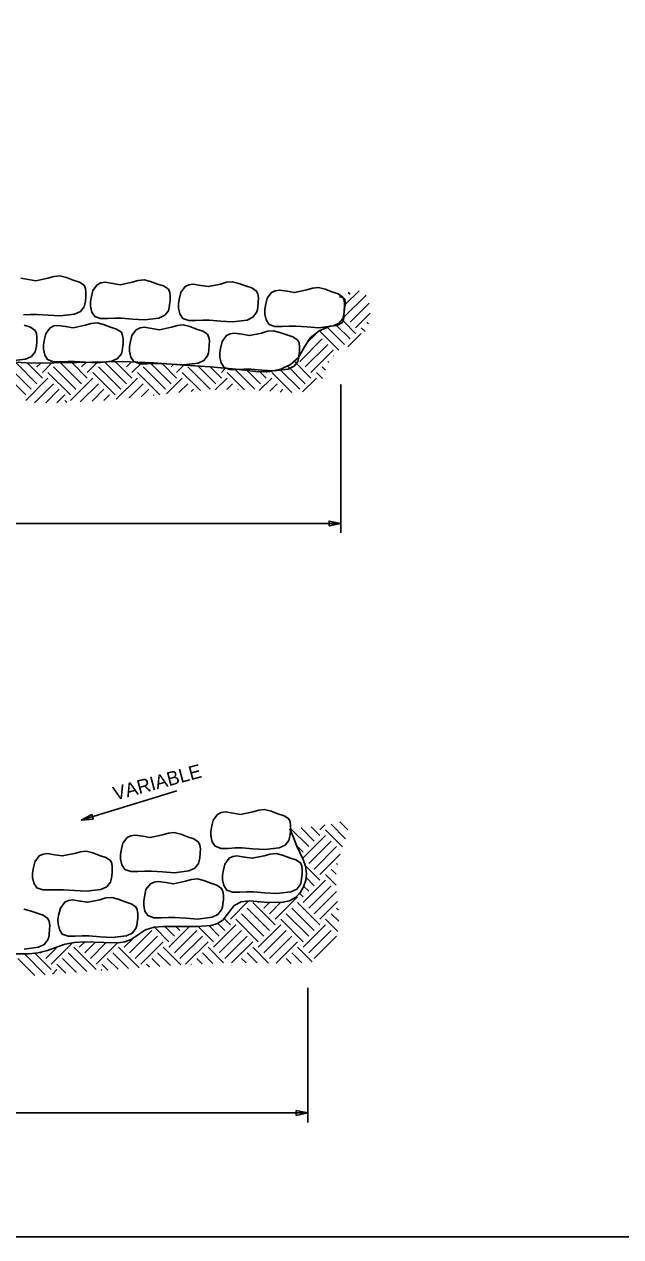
# Model space of a CAD drawing. Extents: x -439.1 to -407.9, y -458.1 to -436.2.
# Drawn here: x -424.86 to -418.4, y -458.05 to -444.91 of the extents above; entities that cross this region are included whole.
import ezdxf

# ---------------------------------------------------------------- set-up
doc = ezdxf.new("R2010")
doc.units = 0
doc.layers.add('Draft_Named_Boundary', color=7, linetype='Continuous')
doc.layers.add('Level 4', color=7, linetype='Continuous')

msp = doc.modelspace()

# ---------------------------------------------------------------- linework, layer by layer
at = {"layer": 'Draft_Named_Boundary'}
msp.add_lwpolyline([(-439.109, -458.051), (-407.859, -458.051), (-407.859, -437.676), (-439.109, -437.676)], close=True, dxfattribs=at)
at = {"layer": 'Level 4'}
for p, q in [((-421.415, -447.871), (-421.429, -447.856)), ((-421.389, -448.078), (-421.155, -447.844)), ((-421.38, -447.947), (-421.231, -447.798)), ((-421.329, -447.835), (-421.348, -447.816)), ((-421.329, -448.138), (-421.121, -447.931)), ((-421.268, -448.26), (-421.405, -448.123)), ((-421.268, -448.199), (-421.111, -448.042)), ((-421.799, -448.366), (-421.692, -448.26)), ((-421.45, -448.441), (-421.66, -448.231)), ((-421.389, -448.381), (-421.578, -448.193)), ((-421.329, -448.32), (-421.474, -448.174)), ((-421.352, -448.404), (-421.208, -448.26)), ((-421.166, -448.241), (-421.208, -448.199)), ((-421.129, -448.156), (-421.147, -448.138)), ((-421.874, -448.563), (-421.632, -448.32)), ((-421.814, -448.623), (-421.571, -448.381)), ((-421.753, -448.684), (-421.511, -448.441)), ((-421.508, -448.505), (-421.511, -448.502)), ((-424.784, -448.866), (-425.026, -448.623)), ((-424.723, -448.805), (-424.952, -448.576)), ((-424.663, -448.744), (-424.824, -448.583)), ((-424.723, -448.623), (-424.685, -448.585)), ((-424.663, -448.684), (-424.563, -448.584)), ((-424.299, -448.866), (-424.541, -448.623)), ((-424.238, -448.805), (-424.462, -448.581)), ((-424.178, -448.744), (-424.345, -448.577)), ((-424.238, -448.623), (-424.185, -448.57)), ((-424.178, -448.684), (-424.06, -448.566)), ((-423.814, -448.866), (-424.056, -448.623)), ((-423.753, -448.805), (-423.994, -448.564)), ((-423.693, -448.744), (-423.874, -448.563)), ((-423.753, -448.623), (-423.698, -448.568)), ((-423.693, -448.684), (-423.583, -448.574)), ((-423.329, -448.866), (-423.571, -448.623)), ((-423.268, -448.805), (-423.495, -448.578)), ((-423.208, -448.744), (-423.365, -448.587)), ((-423.268, -448.623), (-423.242, -448.596)), ((-423.208, -448.684), (-423.129, -448.605)), ((-422.844, -448.866), (-423.087, -448.623)), ((-422.783, -448.805), (-422.974, -448.615)), ((-422.723, -448.744), (-422.844, -448.623)), ((-422.723, -448.684), (-422.677, -448.638)), ((-422.359, -448.866), (-422.578, -448.647)), ((-421.874, -448.866), (-422.09, -448.65)), ((-421.814, -448.805), (-422.003, -448.615)), ((-421.753, -448.744), (-421.932, -448.565)), ((-421.595, -448.66), (-421.632, -448.623)), ((-421.56, -448.574), (-421.571, -448.563)), ((-424.844, -448.926), (-425.087, -448.684)), ((-424.844, -448.987), (-424.602, -448.744)), ((-424.359, -448.926), (-424.602, -448.684)), ((-424.359, -448.987), (-424.117, -448.744)), ((-423.875, -448.926), (-424.117, -448.684)), ((-423.862, -448.974), (-423.632, -448.744)), ((-423.391, -448.925), (-423.632, -448.684)), ((-423.319, -448.916), (-423.147, -448.744)), ((-422.951, -448.88), (-423.147, -448.684)), ((-422.79, -448.873), (-422.662, -448.744)), ((-422.474, -448.872), (-422.662, -448.684)), ((-422.299, -448.805), (-422.439, -448.664)), ((-422.312, -448.879), (-422.177, -448.744)), ((-422.238, -448.744), (-422.308, -448.675)), ((-422.238, -448.684), (-422.227, -448.673)), ((-421.959, -448.902), (-422.177, -448.684)), ((-421.843, -448.895), (-421.692, -448.744)), ((-421.628, -448.748), (-421.692, -448.684)), ((-424.748, -449.011), (-424.541, -448.805)), ((-424.627, -449.012), (-424.481, -448.866)), ((-424.253, -449.001), (-424.056, -448.805)), ((-424.125, -448.995), (-423.996, -448.866)), ((-423.727, -448.961), (-423.571, -448.805)), ((-423.593, -448.948), (-423.511, -448.866)), ((-423.183, -448.902), (-423.087, -448.805)), ((-423.049, -448.889), (-423.026, -448.866)), ((-422.664, -448.868), (-422.602, -448.805)), ((-422.544, -448.869), (-422.541, -448.866)), ((-422.198, -448.887), (-422.117, -448.805)), ((-422.087, -448.896), (-422.056, -448.866)), ((-421.43, -448.814), (-421.43, -450.423)), ((-424.507, -449.014), (-424.42, -448.926)), ((-424.398, -449.009), (-424.42, -448.987)), ((-423.996, -448.987), (-423.935, -448.926)), ((-423.457, -448.933), (-423.45, -448.926)), ((-421.43, -450.321), (-436.149, -450.321)), ((-424.241, -453.535), (-423.205, -453.219)), ((-421.777, -453.822), (-421.972, -453.628)), ((-421.717, -453.762), (-421.86, -453.619)), ((-421.656, -453.701), (-421.749, -453.608)), ((-421.656, -453.64), (-421.601, -453.586)), ((-421.41, -453.826), (-421.596, -453.64)), ((-421.378, -453.737), (-421.535, -453.58)), ((-421.354, -453.639), (-421.439, -453.555)), ((-421.838, -453.943), (-421.596, -453.701)), ((-421.777, -454.004), (-421.535, -453.762)), ((-421.838, -453.883), (-421.903, -453.818)), ((-421.717, -454.065), (-421.474, -453.822)), ((-421.656, -454.125), (-421.437, -453.906)), ((-421.656, -454.186), (-421.821, -454.021)), ((-421.463, -454.015), (-421.474, -454.004)), ((-421.717, -454.246), (-421.809, -454.155)), ((-421.48, -454.241), (-421.596, -454.125)), ((-421.48, -454.12), (-421.535, -454.065)), ((-421.838, -454.428), (-421.596, -454.186)), ((-421.777, -454.307), (-421.831, -454.254)), ((-421.777, -454.489), (-421.535, -454.246)), ((-422.626, -454.61), (-422.431, -454.415)), ((-422.141, -454.671), (-422.384, -454.428)), ((-422.323, -454.428), (-422.312, -454.418)), ((-422.262, -454.489), (-422.2, -454.427)), ((-422.202, -454.55), (-422.078, -454.426)), ((-422.141, -454.61), (-421.899, -454.368)), ((-421.656, -454.671), (-421.899, -454.428)), ((-421.838, -454.368), (-421.882, -454.324)), ((-421.717, -454.55), (-421.476, -454.308)), ((-421.656, -454.61), (-421.464, -454.418)), ((-422.262, -454.792), (-422.505, -454.55)), ((-422.202, -454.731), (-422.444, -454.489)), ((-421.777, -454.792), (-422.02, -454.55)), ((-421.717, -454.731), (-421.959, -454.489)), ((-421.452, -454.632), (-421.535, -454.55)), ((-421.453, -454.51), (-421.474, -454.489)), ((-423.293, -454.853), (-423.449, -454.696)), ((-423.232, -454.792), (-423.336, -454.688)), ((-423.293, -454.913), (-423.068, -454.688)), ((-423.172, -454.731), (-423.216, -454.687)), ((-422.808, -454.853), (-422.973, -454.687)), ((-422.747, -454.792), (-422.86, -454.679)), ((-422.808, -454.913), (-422.565, -454.671)), ((-422.687, -454.731), (-422.77, -454.648)), ((-422.626, -454.671), (-422.694, -454.603)), ((-422.323, -454.853), (-422.565, -454.61)), ((-422.323, -454.913), (-422.08, -454.671)), ((-421.838, -454.853), (-422.08, -454.61)), ((-421.838, -454.913), (-421.596, -454.671)), ((-421.462, -454.743), (-421.596, -454.61)), ((-423.778, -454.913), (-423.677, -454.813)), ((-423.717, -454.974), (-423.475, -454.731)), ((-423.656, -455.034), (-423.414, -454.792)), ((-423.232, -454.974), (-422.99, -454.731)), ((-423.172, -455.034), (-422.929, -454.792)), ((-422.747, -454.974), (-422.505, -454.731)), ((-422.687, -455.034), (-422.444, -454.792)), ((-422.262, -454.974), (-422.02, -454.731)), ((-422.202, -455.034), (-421.959, -454.792)), ((-421.777, -454.974), (-421.535, -454.731)), ((-421.717, -455.034), (-421.474, -454.792)), ((-424.687, -454.974), (-424.674, -454.961)), ((-424.626, -455.034), (-424.503, -454.911)), ((-424.566, -455.095), (-424.341, -454.87)), ((-424.081, -455.156), (-424.323, -454.913)), ((-424.263, -454.913), (-424.203, -454.854)), ((-424.202, -454.974), (-424.087, -454.859)), ((-424.141, -455.034), (-423.97, -454.863)), ((-424.081, -455.095), (-423.85, -454.865)), ((-423.615, -455.136), (-423.838, -454.913)), ((-423.778, -454.853), (-423.781, -454.849)), ((-423.596, -455.095), (-423.353, -454.853)), ((-423.161, -455.105), (-423.353, -454.913)), ((-423.111, -455.095), (-422.868, -454.853)), ((-422.699, -455.082), (-422.868, -454.913)), ((-422.614, -455.083), (-422.384, -454.853)), ((-422.213, -455.084), (-422.384, -454.913)), ((-422.13, -455.084), (-421.899, -454.853)), ((-421.741, -455.071), (-421.899, -454.913)), ((-424.744, -455.22), (-424.929, -455.034)), ((-424.632, -455.211), (-424.857, -454.985)), ((-424.566, -455.156), (-424.747, -454.974)), ((-424.294, -455.185), (-424.444, -455.034)), ((-424.181, -455.177), (-424.384, -454.974)), ((-423.842, -455.152), (-423.96, -455.034)), ((-423.728, -455.144), (-423.899, -454.974)), ((-423.389, -455.12), (-423.475, -455.034)), ((-423.276, -455.112), (-423.414, -454.974)), ((-422.93, -455.094), (-422.99, -455.034)), ((-422.815, -455.088), (-422.929, -454.974)), ((-422.456, -455.083), (-422.505, -455.034)), ((-422.335, -455.083), (-422.444, -454.974)), ((-421.966, -455.088), (-422.02, -455.034)), ((-421.85, -455.083), (-421.959, -454.974)), ((-424.554, -455.205), (-424.505, -455.156)), ((-424.407, -455.193), (-424.505, -455.095)), ((-424.03, -455.166), (-424.02, -455.156)), ((-423.955, -455.16), (-424.02, -455.095)), ((-423.502, -455.128), (-423.535, -455.095)), ((-423.046, -455.1), (-423.05, -455.095)), ((-421.785, -455.352), (-421.785, -456.812)), ((-421.785, -456.709), (-435.084, -456.709))]:
    msp.add_line(p, q, dxfattribs=at)
for points in [[(-424.897, -447.663), (-424.815, -447.675), (-424.733, -447.689), (-424.602, -447.661), (-424.537, -447.642), (-424.473, -447.637), (-424.403, -447.655), (-424.329, -447.683), (-424.262, -447.703), (-424.211, -447.738), (-424.196, -447.772), (-424.191, -447.811), (-424.192, -447.86), (-424.197, -447.909), (-424.202, -447.942), (-424.211, -447.972), (-424.251, -448.022), (-424.314, -448.052), (-424.47, -448.07), (-424.6, -448.063), (-424.72, -448.054), (-424.792, -448.054), (-424.868, -448.057)], [(-421.548, -448.181), (-421.473, -448.176), (-421.414, -448.145), (-421.4, -448.117), (-421.395, -448.082), (-421.391, -448), (-421.377, -447.939), (-421.385, -447.89), (-421.41, -447.872), (-421.442, -447.862)], [(-421.548, -448.181), (-421.664, -448.231), (-421.76, -448.308), (-421.825, -448.413), (-421.888, -448.521), (-421.973, -448.598), (-422.079, -448.648), (-422.198, -448.673), (-422.32, -448.675), (-422.567, -448.648), (-422.845, -448.623), (-423.119, -448.606), (-423.459, -448.58), (-423.799, -448.563), (-424.288, -448.575), (-424.776, -448.584), (-425.211, -448.556)], [(-424.86, -448.171), (-424.793, -448.192), (-424.741, -448.227), (-424.727, -448.26), (-424.722, -448.299), (-424.723, -448.349), (-424.728, -448.398), (-424.733, -448.43), (-424.741, -448.46), (-424.781, -448.51), (-424.845, -448.54), (-425.001, -448.559)], [(-421.98, -453.628), (-421.943, -453.722), (-421.904, -453.816), (-421.836, -453.961), (-421.81, -454.035), (-421.799, -454.113), (-421.807, -454.187), (-421.832, -454.259), (-421.871, -454.323), (-421.921, -454.374), (-421.985, -454.409), (-422.057, -454.426), (-422.218, -454.427), (-422.42, -454.411), (-422.51, -454.422), (-422.584, -454.461), (-422.645, -454.539), (-422.706, -454.618), (-422.765, -454.656), (-422.834, -454.677), (-422.985, -454.688), (-423.17, -454.687), (-423.352, -454.688), (-423.45, -454.696), (-423.544, -454.723), (-423.623, -454.775), (-423.7, -454.828), (-423.769, -454.853), (-423.842, -454.865), (-423.997, -454.863), (-424.211, -454.854), (-424.315, -454.86), (-424.416, -454.88), (-424.511, -454.914), (-424.608, -454.95), (-424.709, -454.974), (-424.814, -454.985), (-425.026, -454.985)], [(-424.865, -454.499), (-424.795, -454.517), (-424.721, -454.545), (-424.653, -454.566), (-424.602, -454.601), (-424.588, -454.635), (-424.583, -454.673), (-424.584, -454.723), (-424.589, -454.772), (-424.594, -454.804), (-424.602, -454.834), (-424.642, -454.884), (-424.706, -454.914), (-424.862, -454.933)]]:
    msp.add_lwpolyline(points, dxfattribs=at)
for points in [[(-424.135, -447.873), (-424.117, -447.794), (-424.07, -447.732), (-424.029, -447.712), (-423.984, -447.705), (-423.901, -447.718), (-423.82, -447.732), (-423.689, -447.704), (-423.624, -447.685), (-423.56, -447.679), (-423.49, -447.697), (-423.416, -447.725), (-423.349, -447.746), (-423.297, -447.781), (-423.283, -447.815), (-423.278, -447.853), (-423.279, -447.903), (-423.284, -447.952), (-423.289, -447.984), (-423.297, -448.014), (-423.337, -448.064), (-423.401, -448.094), (-423.557, -448.113), (-423.687, -448.106), (-423.807, -448.096), (-423.878, -448.096), (-423.955, -448.1), (-424.032, -448.1), (-424.096, -448.077), (-424.128, -448.028), (-424.142, -447.965), (-424.143, -447.918), (-424.135, -447.873)], [(-423.18, -447.894), (-423.161, -447.816), (-423.114, -447.753), (-423.074, -447.733), (-423.029, -447.727), (-422.946, -447.739), (-422.864, -447.753), (-422.733, -447.725), (-422.668, -447.706), (-422.605, -447.7), (-422.534, -447.718), (-422.46, -447.746), (-422.393, -447.767), (-422.342, -447.802), (-422.327, -447.836), (-422.322, -447.874), (-422.323, -447.924), (-422.329, -447.973), (-422.333, -448.005), (-422.342, -448.035), (-422.382, -448.085), (-422.445, -448.115), (-422.601, -448.134), (-422.731, -448.127), (-422.851, -448.118), (-422.923, -448.118), (-422.999, -448.121), (-423.076, -448.121), (-423.14, -448.098), (-423.172, -448.049), (-423.186, -447.986), (-423.187, -447.939), (-423.18, -447.894)], [(-422.245, -447.958), (-422.227, -447.879), (-422.18, -447.817), (-422.139, -447.797), (-422.094, -447.79), (-422.011, -447.803), (-421.93, -447.817), (-421.798, -447.789), (-421.734, -447.77), (-421.67, -447.764), (-421.6, -447.782), (-421.526, -447.81), (-421.459, -447.831), (-421.407, -447.866), (-421.393, -447.899), (-421.388, -447.938), (-421.389, -447.988), (-421.394, -448.037), (-421.399, -448.069), (-421.407, -448.099), (-421.447, -448.149), (-421.511, -448.179), (-421.667, -448.198), (-421.797, -448.19), (-421.917, -448.181), (-421.988, -448.181), (-422.065, -448.185), (-422.142, -448.185), (-422.206, -448.162), (-422.238, -448.113), (-422.252, -448.05), (-422.253, -448.003), (-422.245, -447.958)], [(-424.645, -448.34), (-424.627, -448.261), (-424.579, -448.199), (-424.539, -448.179), (-424.494, -448.173), (-424.411, -448.185), (-424.33, -448.199), (-424.198, -448.171), (-424.133, -448.152), (-424.07, -448.146), (-423.999, -448.164), (-423.925, -448.192), (-423.858, -448.213), (-423.807, -448.248), (-423.793, -448.282), (-423.787, -448.32), (-423.788, -448.37), (-423.794, -448.419), (-423.799, -448.451), (-423.807, -448.481), (-423.847, -448.531), (-423.91, -448.561), (-424.067, -448.58), (-424.197, -448.573), (-424.316, -448.564), (-424.388, -448.564), (-424.464, -448.567), (-424.541, -448.567), (-424.606, -448.544), (-424.638, -448.495), (-424.652, -448.432), (-424.652, -448.385), (-424.645, -448.34)], [(-423.711, -448.361), (-423.692, -448.283), (-423.645, -448.22), (-423.604, -448.201), (-423.559, -448.194), (-423.477, -448.206), (-423.395, -448.22), (-423.264, -448.192), (-423.199, -448.173), (-423.136, -448.167), (-423.065, -448.186), (-422.991, -448.213), (-422.924, -448.234), (-422.873, -448.269), (-422.858, -448.303), (-422.853, -448.342), (-422.854, -448.391), (-422.86, -448.44), (-422.864, -448.472), (-422.873, -448.503), (-422.913, -448.553), (-422.976, -448.583), (-423.132, -448.601), (-423.262, -448.594), (-423.382, -448.585), (-423.454, -448.585), (-423.53, -448.588), (-423.607, -448.588), (-423.671, -448.565), (-423.703, -448.516), (-423.717, -448.453), (-423.718, -448.406), (-423.711, -448.361)], [(-422.734, -448.425), (-422.715, -448.346), (-422.668, -448.284), (-422.628, -448.264), (-422.583, -448.257), (-422.5, -448.27), (-422.418, -448.284), (-422.287, -448.256), (-422.222, -448.237), (-422.159, -448.231), (-422.088, -448.249), (-422.014, -448.277), (-421.947, -448.298), (-421.896, -448.333), (-421.881, -448.367), (-421.876, -448.405), (-421.877, -448.455), (-421.883, -448.504), (-421.887, -448.536), (-421.896, -448.566), (-421.936, -448.616), (-421.999, -448.646), (-422.155, -448.665), (-422.285, -448.658), (-422.405, -448.648), (-422.477, -448.649), (-422.553, -448.652), (-422.63, -448.652), (-422.694, -448.629), (-422.726, -448.58), (-422.74, -448.517), (-422.741, -448.47), (-422.734, -448.425)], [(-421.556, -450.347), (-421.43, -450.321), (-421.556, -450.294)], [(-424.128, -453.473), (-424.241, -453.535), (-424.113, -453.524)], [(-424.128, -453.473), (-424.241, -453.535), (-424.113, -453.524)], [(-422.83, -453.614), (-422.812, -453.535), (-422.764, -453.473), (-422.724, -453.453), (-422.679, -453.446), (-422.596, -453.459), (-422.515, -453.473), (-422.383, -453.445), (-422.318, -453.426), (-422.255, -453.42), (-422.185, -453.438), (-422.111, -453.466), (-422.043, -453.487), (-421.992, -453.522), (-421.978, -453.555), (-421.973, -453.594), (-421.974, -453.644), (-421.979, -453.693), (-421.984, -453.725), (-421.992, -453.755), (-422.032, -453.805), (-422.096, -453.835), (-422.252, -453.854), (-422.382, -453.846), (-422.502, -453.837), (-422.573, -453.837), (-422.649, -453.841), (-422.727, -453.841), (-422.791, -453.818), (-422.823, -453.769), (-422.837, -453.706), (-422.838, -453.659), (-422.83, -453.614)], [(-423.809, -453.865), (-423.791, -453.786), (-423.743, -453.724), (-423.703, -453.704), (-423.658, -453.697), (-423.575, -453.71), (-423.494, -453.724), (-423.362, -453.696), (-423.297, -453.677), (-423.234, -453.671), (-423.163, -453.689), (-423.089, -453.717), (-423.022, -453.738), (-422.971, -453.773), (-422.957, -453.806), (-422.951, -453.845), (-422.952, -453.895), (-422.958, -453.944), (-422.963, -453.976), (-422.971, -454.006), (-423.011, -454.056), (-423.074, -454.086), (-423.231, -454.105), (-423.361, -454.097), (-423.48, -454.088), (-423.552, -454.088), (-423.628, -454.092), (-423.705, -454.092), (-423.77, -454.069), (-423.802, -454.02), (-423.816, -453.957), (-423.816, -453.91), (-423.809, -453.865)], [(-424.763, -454.066), (-424.744, -453.987), (-424.697, -453.924), (-424.656, -453.905), (-424.611, -453.898), (-424.529, -453.91), (-424.447, -453.924), (-424.316, -453.896), (-424.251, -453.878), (-424.188, -453.872), (-424.117, -453.89), (-424.043, -453.918), (-423.976, -453.939), (-423.925, -453.974), (-423.91, -454.007), (-423.905, -454.046), (-423.906, -454.095), (-423.912, -454.144), (-423.916, -454.177), (-423.925, -454.207), (-423.965, -454.257), (-424.028, -454.287), (-424.184, -454.305), (-424.314, -454.298), (-424.434, -454.289), (-424.506, -454.289), (-424.582, -454.292), (-424.659, -454.292), (-424.723, -454.269), (-424.755, -454.22), (-424.769, -454.158), (-424.77, -454.111), (-424.763, -454.066)], [(-422.705, -454.091), (-422.686, -454.012), (-422.639, -453.949), (-422.599, -453.93), (-422.554, -453.923), (-422.471, -453.935), (-422.389, -453.949), (-422.258, -453.921), (-422.193, -453.903), (-422.13, -453.897), (-422.059, -453.915), (-421.985, -453.943), (-421.918, -453.964), (-421.867, -453.999), (-421.852, -454.032), (-421.847, -454.071), (-421.848, -454.121), (-421.854, -454.17), (-421.858, -454.202), (-421.867, -454.232), (-421.907, -454.282), (-421.97, -454.312), (-422.126, -454.331), (-422.256, -454.323), (-422.376, -454.314), (-422.448, -454.314), (-422.524, -454.317), (-422.601, -454.317), (-422.665, -454.294), (-422.698, -454.245), (-422.711, -454.183), (-422.712, -454.136), (-422.705, -454.091)], [(-423.558, -454.367), (-423.54, -454.288), (-423.492, -454.225), (-423.452, -454.206), (-423.407, -454.199), (-423.324, -454.212), (-423.243, -454.225), (-423.111, -454.198), (-423.046, -454.179), (-422.983, -454.173), (-422.912, -454.191), (-422.838, -454.219), (-422.771, -454.24), (-422.72, -454.275), (-422.706, -454.308), (-422.7, -454.347), (-422.701, -454.397), (-422.707, -454.446), (-422.712, -454.478), (-422.72, -454.508), (-422.76, -454.558), (-422.823, -454.588), (-422.98, -454.607), (-423.11, -454.599), (-423.229, -454.59), (-423.301, -454.59), (-423.377, -454.593), (-423.454, -454.593), (-423.519, -454.57), (-423.551, -454.521), (-423.565, -454.459), (-423.565, -454.412), (-423.558, -454.367)], [(-424.487, -454.568), (-424.468, -454.489), (-424.421, -454.426), (-424.38, -454.407), (-424.335, -454.4), (-424.253, -454.412), (-424.171, -454.426), (-424.04, -454.398), (-423.975, -454.379), (-423.912, -454.374), (-423.841, -454.392), (-423.767, -454.42), (-423.7, -454.441), (-423.649, -454.475), (-423.634, -454.509), (-423.629, -454.548), (-423.63, -454.597), (-423.636, -454.646), (-423.64, -454.679), (-423.649, -454.709), (-423.689, -454.759), (-423.752, -454.789), (-423.908, -454.807), (-424.038, -454.8), (-424.158, -454.791), (-424.23, -454.791), (-424.306, -454.794), (-424.383, -454.794), (-424.447, -454.771), (-424.479, -454.722), (-424.493, -454.66), (-424.494, -454.613), (-424.487, -454.568)], [(-421.911, -456.735), (-421.785, -456.709), (-421.911, -456.683)]]:
    msp.add_lwpolyline(points, close=True, dxfattribs=at)

# ---------------------------------------------------------------- texts
msp.add_text('VARIABLE', height=0.15, rotation=15, dxfattribs=at).set_placement((-423.874, -453.324))

doc.saveas('drawing.dxf')
